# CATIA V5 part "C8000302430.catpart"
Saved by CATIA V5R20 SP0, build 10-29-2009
Part number: C8000302430
Source: Unknown
Property "A": "40"
Property "ARTICLENO": "C8000302430"
Property "B": "18"
Property "BOMINFO": "C8000302430"
Property "C": "70"
Property "CA": "C8000302430"
Property "D1": "58"
Property "DES": "ROTATING EYEBOLT WITH RING Ton 3,15 M24x30"
Property "E": "68"
Property "H": "153"
Property "L": "30"
Property "LINA": "C8000302430"
Property "NB": "C8000302430"
Property "NBSYN": "$CODE."
Property "NN": "C800"
Property "NT": "Rotating eyebolt with ring"
Property "SIZE": "M24"
Property "SUPPLIER": "CF"
Property "SW": "48"
Property "WEIGHT": "1630"
Property "WLL": "3.15"
Bounding box of the stored display mesh (mm): x -38 to 38, y -30 to 171, z -29 to 29
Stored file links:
  C:\Users\Utente\Desktop\3D files 800\C8000302430.catpart
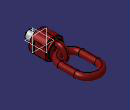
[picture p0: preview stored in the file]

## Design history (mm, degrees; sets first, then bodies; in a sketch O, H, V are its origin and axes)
Body1 "Geometry.1" (main body)
  Solid1 "C8000302430.catpart": solid without history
